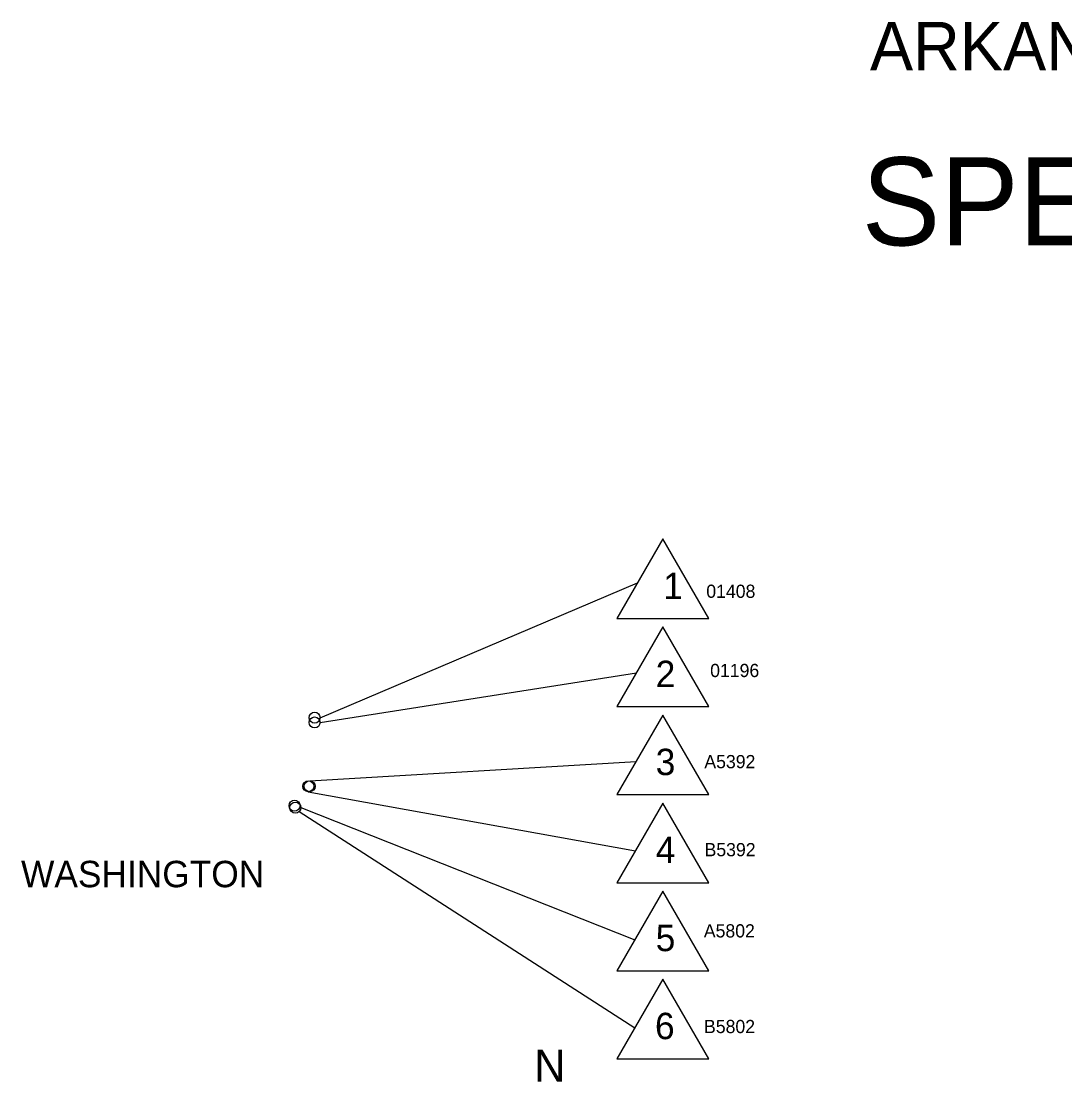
# Model space of a CAD drawing. Extents: x -35254 to 17396, y -8913 to 11592.
# Drawn here: x -11717 to -2230, y 1953 to 11592 of the extents above; entities that cross this region are included whole.
import ezdxf

# ---------------------------------------------------------------- set-up
doc = ezdxf.new("R2010")
doc.units = 0
for name, color, linetype in [('2', 7, 'Continuous'), ('R_Annotation', 7, 'Continuous'), ('R_No Plot', 7, 'Continuous')]:
    doc.layers.add(name, color=color, linetype=linetype)

msp = doc.modelspace()

# ---------------------------------------------------------------- linework, layer by layer
at = {"layer": 'R_Annotation'}
for p, q in [((-5883.9, 6886.3), (-6301.8, 6162.4)), ((-5466, 6162.4), (-5883.9, 6886.3)), ((-9000.3, 5261.8), (-6113.4, 6488.8)), ((-6301.8, 6162.4), (-5466, 6162.4)), ((-5883.9, 6086.3), (-6301.8, 5362.4)), ((-5466, 5362.4), (-5883.9, 6086.3)), ((-9000.3, 5218.6), (-6125, 5668.8)), ((-6301.8, 5362.4), (-5466, 5362.4)), ((-5883.9, 5286.3), (-6301.8, 4562.4)), ((-5466, 4562.4), (-5883.9, 5286.3)), ((-9094.8, 4688.7), (-6127.7, 4864.1)), ((-9107.4, 4588.9), (-6134, 4053.1)), ((-6301.8, 4562.4), (-5466, 4562.4)), ((-9175, 4444.4), (-6139.3, 3244)), ((-5883.9, 4486.3), (-6301.8, 3762.4)), ((-5466, 3762.4), (-5883.9, 4486.3)), ((-9189.7, 4409), (-6139.3, 2444)), ((-6301.8, 3762.4), (-5466, 3762.4)), ((-5883.9, 3686.3), (-6301.8, 2962.4)), ((-5466, 2962.4), (-5883.9, 3686.3)), ((-6301.8, 2962.4), (-5466, 2962.4)), ((-5883.9, 2886.3), (-6301.8, 2162.4)), ((-5466, 2162.4), (-5883.9, 2886.3)), ((-6301.8, 2162.4), (-5466, 2162.4))]:
    msp.add_line(p, q, dxfattribs=at)
for centre in [(-9050.3, 5261.8), (-9050.3, 5218.6), (-9107.4, 4638.9), (-9107.4, 4638.9), (-9094.8, 4638.7), (-9232.7, 4462.8), (-9225, 4444.4)]:
    msp.add_circle(centre, 50, dxfattribs=at)

# ---------------------------------------------------------------- texts
at = {"layer": '2'}
for s, height, p in [('ARKANSAS DEPARTMENT OF TRANSPORTATION', 440, (-4001.5, 11145.7)), ('SPECIALIZED BRIDGE DECK ', 800, (-4076, 9554.9)), ('WASHINGTON', 240, (-11718.6, 3721))]:
    msp.add_text(s, height=height, dxfattribs=at).set_placement(p)
at = {"layer": 'R_Annotation'}
for s, height, p in [('1', 240, (-5881.2, 6340)), ('2', 240, (-5949.2, 5540)), ('3', 240, (-5949.2, 4740)), ('4', 240, (-5949.2, 3940)), ('5', 240, (-5949.2, 3140)), ('6', 240, (-5955.8, 2340)), ('N', 293.3, (-7053.3, 1952.6))]:
    msp.add_text(s, height=height, dxfattribs=at).set_placement(p)
at = {"layer": 'R_No Plot'}
for s, p in [('01408', (-5489.3, 6351.1)), ('01196', (-5453.9, 5631.1)), ('A5392', (-5507, 4802.6)), ('B5392', (-5505.1, 4002.6)), ('A5802', (-5511.7, 3264.5)), ('B5802', (-5509.9, 2395.1))]:
    msp.add_text(s, height=120, dxfattribs=at).set_placement(p)

doc.saveas('drawing.dxf')
